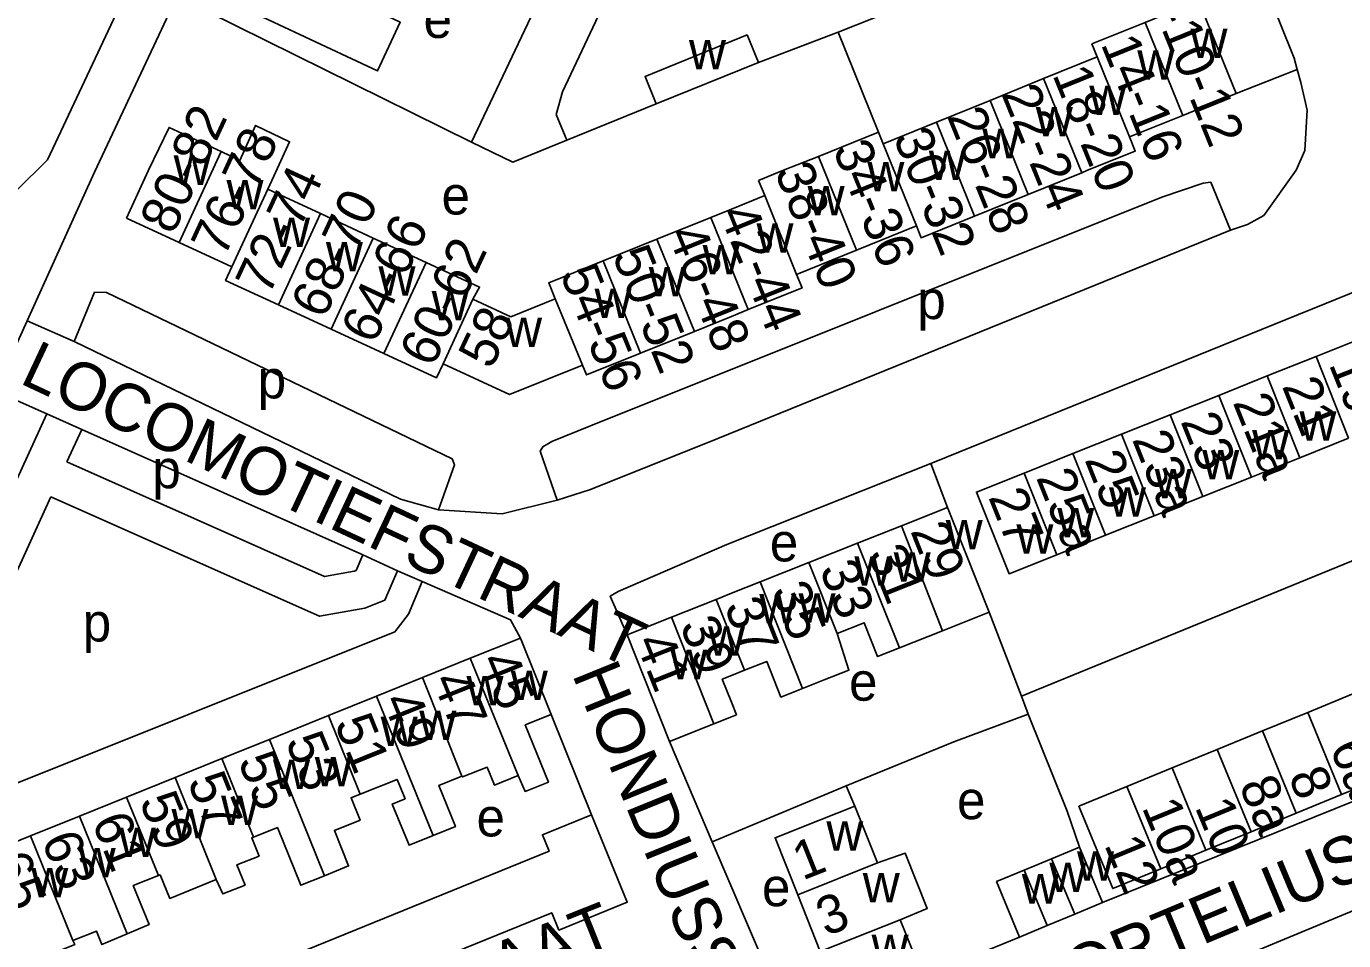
# Model space of a CAD drawing. Extents: x 163026 to 166241, y 382475 to 384501.
# Drawn here: x 163806.9 to 163944.7, y 383919.4 to 384015.1 of the extents above; entities that cross this region are included whole.
import ezdxf

# ---------------------------------------------------------------- set-up
doc = ezdxf.new("R2010")
doc.units = 0
for name, color, linetype in [('BLT_Basislijn', 7, 'Continuous'), ('BLT_Bebouwing', 7, 'Continuous'), ('BLT_Centroide', 7, 'Continuous'), ('BLT_Huisnummer', 7, 'Continuous'), ('BLT_Huisnummer_ tussenligend', 7, 'Continuous'), ('BLT_Huisnummer_reeks', 7, 'Continuous'), ('BLT_Huisnummer_zonder_bebouwing', 7, 'Continuous'), ('BLT_Onderverdeling_panden', 7, 'Continuous'), ('BLT_Plantopo', 7, 'Continuous'), ('BLT_Straatnaam', 7, 'Continuous')]:
    doc.layers.add(name, color=color, linetype=linetype)

msp = doc.modelspace()

# ---------------------------------------------------------------- linework, layer by layer
at = {"layer": 'BLT_Basislijn'}
for p, q in [((163822.68, 384018.2), (163814.06, 383999.82)), ((163853.46, 384002.93), (163822.68, 384018.2)), ((163883.46, 384011.27), (163891.79, 384014.44)), ((163891.79, 384014.44), (163896.01, 384003.99)), ((163939.8, 384010.54), (163933.41, 384008.02)), ((163863.43, 384003.15), (163872.79, 384006.94)), ((163814.06, 383999.82), (163812.81, 383997.06)), ((163812.81, 383997.06), (163807.01, 383984.26)), ((163807.01, 383984.26), (163798.24, 383964.9)), ((163807.01, 383984.26), (163811.92, 383982.1)), ((163805.38, 383976.17), (163809.07, 383974.52)), ((163809.07, 383974.52), (163812.72, 383972.89)), ((163812.72, 383972.89), (163811.17, 383969.49)), ((163812.72, 383972.89), (163842.1, 383959.76)), ((163903.22, 383964.72), (163901.49, 383969.32)), ((163910.96, 383944.99), (163964.68, 383966.99)), ((163842.1, 383959.76), (163845.75, 383958.12)), ((163845.75, 383958.12), (163848.3, 383956.98)), ((163907.58, 383953.77), (163910.96, 383944.99)), ((163910.96, 383944.99), (163911.68, 383943.1)), ((163973.09, 383945.13), (163919.45, 383923.39)), ((163861.81, 383943.08), (163866.03, 383932.58)), ((163911.68, 383943.1), (163915.75, 383932.97)), ((163878.64, 383929.76), (163874.16, 383940.26)), ((163878.64, 383929.76), (163892.65, 383935.62)), ((163893.55, 383933.49), (163892.65, 383935.62)), ((163915.75, 383932.97), (163917.04, 383929.2)), ((163887.14, 383909.88), (163878.64, 383929.76)), ((163910.78, 383919.79), (163900.66, 383915.67))]:
    msp.add_line(p, q, dxfattribs=at)
for points in [[(163849.01, 384085.89), (163834.84, 384059.46), (163835.45, 384057.42), (163823.21, 384031.1), (163809.15, 384001.11), (163805.88, 383997.85)], [(163891.79, 384014.44), (163932, 384030.42), (163939.47, 384011.72), (163939.8, 384010.54)], [(163932.83, 383993.75), (163934.6, 383994.33), (163936.29, 383995.28), (163939.69, 384000.03), (163940.6, 384002.07), (163940.83, 384006.3), (163940.18, 384009.18), (163939.8, 384010.54)], [(163932.83, 383993.75), (163930.75, 383998.76), (163929.95, 383998.65), (163925.64, 383997.2), (163865.91, 383973.26), (163861.88, 383971.64), (163860.92, 383971.09), (163860.66, 383970.61), (163862.44, 383965.48)], [(163932.83, 383993.75), (163879.24, 383971.93), (163865.91, 383966.6), (163862.44, 383965.48)], [(163901.49, 383969.32), (163901.85, 383969.47), (163945.25, 383987.07), (163951.25, 383989.73)], [(163850.03, 383964.5), (163851.68, 383969.18), (163851.45, 383969.82), (163815.33, 383987.21), (163814.07, 383987.25), (163811.92, 383982.1)], [(163850.03, 383964.5), (163846.04, 383965.59), (163811.92, 383982.1)], [(163809.07, 383974.52), (163799.29, 383953.15), (163799.06, 383947.15), (163796.84, 383942.1)], [(163811.17, 383969.49), (163838.11, 383957.51), (163841.22, 383958.06), (163841.41, 383958.14), (163842.1, 383959.76)], [(163869.73, 383951.42), (163867.98, 383955.44), (163868.8, 383955.94), (163880.15, 383960.86), (163901.49, 383969.32)], [(163809.5, 383965.86), (163803.25, 383952.2), (163803.02, 383946.24), (163798.77, 383936.55)], [(163809.5, 383965.86), (163837.6, 383953.36), (163842.32, 383954.2), (163844.43, 383955.04), (163845.75, 383958.12)], [(163850.03, 383964.5), (163856.68, 383964.07), (163862.44, 383965.48)], [(163848.3, 383956.98), (163846.88, 383953.58), (163845.46, 383951.72), (163802.6, 383934.57), (163799.82, 383935.23), (163798.77, 383936.55)], [(163858.58, 383951.07), (163857.56, 383952.97), (163848.3, 383956.98)], [(163892.65, 383935.62), (163903.91, 383940.21), (163911.68, 383943.1)], [(163922.9, 383913.1), (163924.05, 383913.58), (163964.39, 383930.36)]]:
    msp.add_lwpolyline(points, dxfattribs=at)
at = {"layer": 'BLT_Bebouwing'}
for p, q in [((163923.89, 384015.48), (163918.32, 384013.22)), ((163918.87, 384011.86), (163918.32, 384013.22)), ((163872.79, 384006.94), (163883.46, 384011.27)), ((163918.87, 384011.86), (163913.27, 384009.59)), ((163913.27, 384009.59), (163907.68, 384007.32)), ((163907.68, 384007.32), (163902.08, 384005.05)), ((163927.83, 384005.75), (163933.41, 384008.02)), ((163922.26, 384003.49), (163927.83, 384005.75)), ((163902.08, 384005.05), (163896.5, 384002.78)), ((163896.01, 384003.99), (163889.75, 384001.46)), ((163896.5, 384002.78), (163896.01, 384003.99)), ((163832.18, 383998.03), (163832.82, 383999.4)), ((163884.13, 383997.36), (163883.49, 383998.94)), ((163917.27, 383999.74), (163911.67, 383997.48)), ((163837.7, 383995.47), (163832.18, 383998.03)), ((163911.67, 383997.48), (163906.07, 383995.21)), ((163822.9, 383992.46), (163817.39, 383995.01)), ((163843.21, 383992.92), (163837.7, 383995.47)), ((163878.5, 383995.08), (163872.86, 383992.8)), ((163899.98, 383994.18), (163893.72, 383991.64)), ((163828.42, 383989.9), (163822.9, 383992.46)), ((163848.72, 383990.37), (163843.21, 383992.92)), ((163872.86, 383992.8), (163867.23, 383990.52)), ((163893.72, 383991.64), (163887.46, 383989.11)), ((163838.79, 383983.39), (163833.28, 383985.94)), ((163844.3, 383980.84), (163838.79, 383983.39)), ((163876.77, 383983.15), (163871.14, 383980.87)), ((163941.76, 383980.52), (163946.84, 383982.55)), ((163936.67, 383978.49), (163941.76, 383980.52)), ((163931.59, 383976.46), (163936.67, 383978.49)), ((163926.51, 383974.43), (163931.59, 383976.46)), ((163921.42, 383972.4), (163926.51, 383974.43)), ((163916.34, 383970.36), (163921.42, 383972.4)), ((163945.17, 383971.97), (163940.08, 383969.94)), ((163911.25, 383968.33), (163916.34, 383970.36)), ((163940.08, 383969.94), (163935, 383967.91)), ((163935, 383967.91), (163929.92, 383965.88)), ((163929.92, 383965.88), (163924.83, 383963.85)), ((163903.22, 383964.72), (163898.43, 383962.82)), ((163924.83, 383963.85), (163919.75, 383961.82)), ((163898.43, 383962.82), (163893.83, 383960.99)), ((163919.75, 383961.82), (163914.67, 383959.79)), ((163893.83, 383960.99), (163888.74, 383958.97)), ((163888.74, 383958.97), (163883.65, 383956.95)), ((163879.06, 383955.12), (163874.38, 383953.27)), ((163874.38, 383953.27), (163869.73, 383951.42)), ((163858.58, 383951.07), (163853.35, 383948.96)), ((163858.58, 383951.07), (163861.81, 383943.08)), ((163869.73, 383951.42), (163874.16, 383940.26)), ((163853.35, 383948.96), (163848.35, 383946.94)), ((163848.35, 383946.94), (163843.55, 383945)), ((163843.55, 383945), (163838.51, 383942.96)), ((163838.51, 383942.96), (163832.34, 383940.47)), ((163874.16, 383940.26), (163878.81, 383942.11)), ((163832.34, 383940.47), (163827.37, 383938.46)), ((163827.38, 383938.46), (163822.48, 383936.48)), ((163827.85, 383938.66), (163827.34, 383938.45)), ((163822.48, 383936.48), (163817.42, 383934.44)), ((163817.42, 383934.44), (163812.48, 383932.44)), ((163895.92, 383927.55), (163893.55, 383933.49)), ((163812.48, 383932.44), (163807.36, 383930.37)), ((163807.36, 383930.37), (163802.03, 383928.22)), ((163917.04, 383929.2), (163919.45, 383923.39)), ((163887.58, 383924.22), (163889.94, 383918.28)), ((163919.45, 383923.39), (163916.54, 383922.18)), ((163916.54, 383922.18), (163913.67, 383920.99)), ((163913.67, 383920.99), (163910.78, 383919.79))]:
    msp.add_line(p, q, dxfattribs=at)
for points in [[(163901.48, 384026.31), (163882.18, 384019.8), (163881.99, 384020.3), (163878.85, 384019.21), (163877.95, 384021.4), (163871.44, 384018.65), (163870.9, 384019.94), (163867.9, 384018.68), (163862.99, 384008.21), (163862.34, 384005.84), (163863.43, 384003.15)], [(163842.83, 384016.99), (163846.03, 384015.49), (163843.65, 384010.4), (163840.45, 384011.9), (163827.33, 384018.08), (163829.69, 384023.13)], [(163853.46, 384002.93), (163863.25, 384023.62)], [(163933.41, 384008.02), (163929.46, 384017.74), (163924.83, 384015.86), (163923.89, 384015.48)], [(163872.79, 384006.94), (163871.62, 384009.83), (163882.28, 384014.16), (163883.46, 384011.27)], [(163817.39, 383995.01), (163819.7, 384000), (163821.85, 384004.49), (163826.4, 384002.38), (163827.31, 384001.96)], [(163827.31, 384001.96), (163829.27, 384001.02), (163830.9, 384004.7), (163834.46, 384002.99), (163832.82, 383999.4)], [(163863.43, 384003.15), (163857.81, 384000.87), (163853.46, 384002.93)], [(163922.26, 384003.49), (163922.86, 384002.02), (163917.87, 384000), (163917.27, 383999.74)], [(163889.75, 384001.46), (163886.1, 384000), (163883.49, 383998.94)], [(163884.13, 383997.36), (163880.64, 383995.95), (163878.5, 383995.08)], [(163906.07, 383995.21), (163900.47, 383992.95), (163899.98, 383994.18)], [(163833.28, 383985.94), (163827.77, 383988.49), (163828.42, 383989.9)], [(163853.63, 383986.52), (163854.31, 383987.78), (163848.72, 383990.37)], [(163867.23, 383990.52), (163861.55, 383988.22), (163862.23, 383986.56)], [(163887.46, 383989.11), (163888.03, 383987.7), (163882.4, 383985.43)], [(163862.23, 383986.56), (163857.59, 383984.68), (163853.63, 383986.52)], [(163882.4, 383985.43), (163880.64, 383984.71), (163876.77, 383983.15)], [(163850.5, 383979.76), (163849.81, 383978.28), (163844.3, 383980.84)], [(163865.08, 383979.63), (163857.44, 383976.54), (163850.5, 383979.76)], [(163871.14, 383980.87), (163865.5, 383978.59), (163865.08, 383979.63)], [(163911.25, 383968.33), (163906.26, 383966.34), (163909.68, 383957.8), (163914.67, 383959.79)], [(163907.58, 383953.77), (163905.07, 383960.08), (163903.22, 383964.72)], [(163883.65, 383956.95), (163880.64, 383955.75), (163879.06, 383955.12)], [(163907.58, 383953.77), (163902.71, 383951.84)], [(163898.23, 383950.06), (163895.92, 383949.14), (163894.52, 383952.67), (163891.69, 383951.54)], [(163891.69, 383951.54), (163892.93, 383947.72), (163890.34, 383946.69), (163888.08, 383945.79)], [(163902.71, 383951.84), (163898.23, 383950.06)], [(163888.08, 383945.79), (163885.82, 383944.89), (163884.34, 383948.62), (163882.01, 383947.7)], [(163882.01, 383947.7), (163880.64, 383947.15), (163879.69, 383946.77), (163880.64, 383944.37), (163881.17, 383943.05), (163880.64, 383942.84), (163878.81, 383942.11)], [(163861.81, 383943.08), (163859.1, 383941.99), (163861.51, 383936.01), (163859.07, 383935.02), (163858.35, 383936.69)], [(163858.35, 383936.69), (163855.87, 383935.69), (163855.1, 383937.57), (163852.54, 383936.54), (163852.48, 383936.64)], [(163849.46, 383930.4), (163846.94, 383929.39), (163845.19, 383933.71), (163846.53, 383934.26), (163845.7, 383936.29), (163841.84, 383934.73)], [(163852.48, 383936.64), (163850.05, 383935.66), (163851.79, 383931.35), (163849.46, 383930.4)], [(163841.84, 383934.73), (163840.88, 383934.34), (163841.83, 383932.01), (163839.14, 383930.93), (163840.63, 383927.24), (163838.1, 383926.21)], [(163893.55, 383933.49), (163889.85, 383932.01), (163885.21, 383930.16), (163887.58, 383924.22)], [(163803.74, 383905.23), (163861.59, 383928.76), (163860.89, 383930.49), (163866.03, 383932.58)], [(163866.03, 383932.58), (163869.75, 383923.44), (163862.61, 383920.53), (163861.87, 383922.34), (163806.02, 383899.63)], [(163830.7, 383930.24), (163830.5, 383930.16), (163831.26, 383928.27), (163828.95, 383927.35), (163829.8, 383925.23), (163827.48, 383924.31), (163826.79, 383925.8)], [(163838.1, 383926.21), (163835.63, 383925.22), (163833.19, 383931.25), (163830.7, 383930.24)], [(163914.12, 383927.99), (163917.04, 383929.2)], [(163898.29, 383921.61), (163901.12, 383922.79), (163898.82, 383928.56), (163895.92, 383927.55)], [(163911.26, 383926.8), (163914.12, 383927.99)], [(163820.74, 383926.23), (163818.12, 383925.17), (163819.77, 383921.09), (163817.46, 383920.12)], [(163826.79, 383925.8), (163821.92, 383923.83), (163820.92, 383926.3), (163820.74, 383926.23)], [(163910.78, 383919.79), (163908.37, 383925.6), (163911.26, 383926.8)], [(163817.46, 383920.12), (163814.84, 383919.01), (163814.27, 383920.42), (163811.79, 383919.42)], [(163900.66, 383915.67), (163898.8, 383920.32), (163898.29, 383921.61)], [(163811.79, 383919.42), (163812, 383919.01), (163806.63, 383916.84), (163805.21, 383920.35)]]:
    msp.add_lwpolyline(points, dxfattribs=at)
at = {"layer": 'BLT_Onderverdeling_panden'}
for p, q in [((163927.83, 384005.75), (163923.89, 384015.48)), ((163922.26, 384003.49), (163918.87, 384011.86)), ((163917.27, 383999.74), (163913.27, 384009.59)), ((163911.67, 383997.48), (163907.68, 384007.32)), ((163906.07, 383995.21), (163902.08, 384005.05)), ((163822.9, 383992.46), (163827.31, 384001.96)), ((163899.98, 383994.18), (163896.5, 384002.78)), ((163893.72, 383991.64), (163889.75, 384001.46)), ((163828.42, 383989.9), (163832.18, 383998.03)), ((163887.46, 383989.11), (163884.13, 383997.36)), ((163833.28, 383985.94), (163837.7, 383995.47)), ((163882.4, 383985.43), (163878.5, 383995.08)), ((163838.79, 383983.39), (163843.21, 383992.92)), ((163876.77, 383983.15), (163872.86, 383992.8)), ((163844.3, 383980.84), (163848.72, 383990.37)), ((163871.14, 383980.87), (163867.23, 383990.52)), ((163853.63, 383986.52), (163850.5, 383979.76)), ((163862.23, 383986.56), (163865.08, 383979.63)), ((163941.76, 383980.52), (163945.17, 383971.97)), ((163940.08, 383969.94), (163936.67, 383978.49)), ((163931.59, 383976.46), (163935, 383967.91)), ((163929.92, 383965.88), (163926.51, 383974.43)), ((163921.42, 383972.4), (163924.83, 383963.85)), ((163919.75, 383961.82), (163916.34, 383970.36)), ((163911.25, 383968.33), (163914.67, 383959.79)), ((163902.71, 383951.84), (163898.43, 383962.82)), ((163898.23, 383950.06), (163893.83, 383960.99)), ((163891.69, 383951.54), (163888.74, 383958.97)), ((163888.08, 383945.79), (163883.65, 383956.95)), ((163882.01, 383947.7), (163879.06, 383955.12)), ((163878.81, 383942.11), (163874.38, 383953.27)), ((163858.35, 383936.69), (163853.35, 383948.96)), ((163852.48, 383936.64), (163848.35, 383946.94)), ((163849.46, 383930.4), (163843.55, 383945)), ((163841.84, 383934.73), (163838.51, 383942.96)), ((163838.1, 383926.21), (163832.34, 383940.47)), ((163830.7, 383930.24), (163827.38, 383938.46)), ((163826.79, 383925.8), (163822.48, 383936.48)), ((163820.74, 383926.23), (163817.42, 383934.44)), ((163817.46, 383920.12), (163812.48, 383932.44)), ((163811.79, 383919.42), (163807.36, 383930.37)), ((163895.92, 383927.55), (163887.58, 383924.22)), ((163916.54, 383922.18), (163914.12, 383927.99)), ((163913.67, 383920.99), (163911.26, 383926.8)), ((163898.29, 383921.61), (163889.94, 383918.28))]:
    msp.add_line(p, q, dxfattribs=at)
at = {"layer": 'BLT_Plantopo'}
for p, q in [((163940.89, 383943.3), (163945.6, 383945.24)), ((163936.17, 383941.36), (163940.89, 383943.3)), ((163940.89, 383943.3), (163944.43, 383934.69)), ((163931.44, 383939.42), (163936.17, 383941.36)), ((163939.7, 383932.75), (163936.17, 383941.36)), ((163926.72, 383937.48), (163931.44, 383939.42)), ((163931.44, 383939.42), (163934.97, 383930.81)), ((163922, 383935.55), (163926.72, 383937.48)), ((163926.72, 383937.48), (163930.25, 383928.87)), ((163925.54, 383926.93), (163922, 383935.55)), ((163944.43, 383934.69), (163949.14, 383936.63)), ((163939.7, 383932.75), (163944.43, 383934.69)), ((163934.97, 383930.81), (163939.7, 383932.75)), ((163930.25, 383928.87), (163934.97, 383930.81)), ((163930.25, 383928.87), (163925.54, 383926.93))]:
    msp.add_line(p, q, dxfattribs=at)
msp.add_lwpolyline([(163922, 383935.55), (163916.98, 383933.48), (163920.51, 383924.87), (163925.54, 383926.93)], dxfattribs=at)

# ---------------------------------------------------------------- texts
at = {"layer": 'BLT_Centroide'}
for s, p in [('e', (163848.46, 384013.85)), ('w', (163928.64, 384011.75)), ('w', (163876.21, 384010.56)), ('w', (163923.08, 384009.48)), ('w', (163918.06, 384005.8)), ('w', (163912.47, 384003.55)), ('w', (163906.88, 384001.27)), ('w', (163901.28, 383999)), ('w', (163822.34, 383998.48)), ('w', (163894.86, 383997.81)), ('w', (163827.86, 383995.92)), ('e', (163850.34, 383995.38)), ('w', (163888.61, 383995.28)), ('w', (163832.73, 383991.98)), ('w', (163883.27, 383991.39)), ('w', (163838.25, 383989.44)), ('w', (163877.64, 383989.11)), ('w', (163843.75, 383986.88)), ('w', (163872, 383986.83)), ('w', (163849.31, 383984.31)), ('w', (163866.34, 383984.55)), ('p', (163900.08, 383984.44)), ('w', (163856.99, 383981.53)), ('p', (163831.12, 383976.14)), ('w', (163940.03, 383971.72)), ('w', (163935.09, 383969.75)), ('w', (163929.87, 383967.66)), ('p', (163820.11, 383966.74)), ('w', (163924.9, 383965.67)), ('w', (163920.12, 383963.77)), ('w', (163914.71, 383961.61)), ('w', (163903.05, 383960.36)), ('e', (163884.66, 383959.09)), ('w', (163910.44, 383959.9)), ('w', (163893.5, 383956.56)), ('w', (163897.61, 383956.98)), ('w', (163883.56, 383952.61)), ('w', (163887.67, 383952.67)), ('p', (163812.83, 383950.71)), ('w', (163878.2, 383949.22)), ('w', (163874.27, 383946.77)), ('w', (163852.95, 383944.02)), ('w', (163857.58, 383944.58)), ('e', (163892.94, 383944.52)), ('w', (163843.98, 383939.77)), ('w', (163848.02, 383940.39)), ('w', (163832.73, 383935.27)), ('w', (163837.09, 383935.55)), ('w', (163827.3, 383931.5)), ('e', (163904.23, 383932.12)), ('w', (163822.11, 383930.12)), ('e', (163854, 383930.32)), ('w', (163890.57, 383928.84)), ('w', (163816.61, 383928.17)), ('w', (163812.41, 383926.05)), ('w', (163916.78, 383925.69)), ('w', (163913.89, 383924.5)), ('w', (163807.45, 383923.95)), ('e', (163883.84, 383923.02)), ('w', (163894.38, 383923.41)), ('w', (163911.02, 383923.3)), ('w', (163895.3, 383916.97))]:
    msp.add_text(s, height=4, dxfattribs=at).set_placement(p)
at = {"layer": 'BLT_Huisnummer'}
for s, rotation, p in [('58', 64.7309, (163855.55, 383979.06)), ('19a', 291.7747, (163943.07, 383979.73)), ('21', 291.7747, (163938.17, 383977.44)), ('21a', 291.7747, (163933.03, 383975.74)), ('23', 291.7747, (163927.57, 383973.75)), ('23a', 291.7747, (163922.5, 383971.87)), ('25', 291.7747, (163917.53, 383969.76)), ('25a', 291.7747, (163912.46, 383967.88)), ('27', 291.7747, (163907.47, 383965.83)), ('29', 291.6596, (163899.32, 383962.29)), ('33', 291.6577, (163889.81, 383958.29)), ('37', 291.6869, (163879.85, 383954.4)), ('41', 291.6658, (163870.56, 383950.69)), ('45', 292.0089, (163854.29, 383948.74)), ('49', 292.0089, (163844.12, 383944.52)), ('53', 292.0089, (163833.98, 383940.27)), ('57', 292.0089, (163823.74, 383936.08)), ('61', 292.0089, (163813.74, 383931.87)), ('1', 21.7339, (163888.07, 383925.68)), ('3', 21.7339, (163890.53, 383919.83))]:
    msp.add_text(s, height=4, rotation=rotation, dxfattribs=at).set_placement(p)
at = {"layer": 'BLT_Huisnummer_ tussenligend'}
for s, rotation, p in [('31', 291.6596, (163894.86, 383959.9)), ('35', 291.6577, (163884.76, 383956.04)), ('39', 291.6869, (163875.22, 383952.42)), ('47', 292.0089, (163849.33, 383946.65)), ('51', 292.0089, (163839.11, 383942.16)), ('55', 292.0089, (163829.02, 383938.22)), ('59', 292.0089, (163818.71, 383934.02)), ('63', 292.0089, (163808.47, 383929.92)), ('65', 292.0089, (163803.25, 383927.77))]:
    msp.add_text(s, height=4, rotation=rotation, dxfattribs=at).set_placement(p)
at = {"layer": 'BLT_Huisnummer_reeks'}
for s, rotation, p in [('8-10-12', 292.1015, (163923.78, 384019.25)), ('14-16', 292.0275, (163919.23, 384013.23)), ('18-20', 292.0741, (163914.17, 384010.02)), ('22-24', 292.0729, (163908.83, 384008.03)), ('80-82', 65.1484, (163822.27, 383993.15)), ('26-28', 292.0682, (163903.16, 384005.66)), ('76-78', 65.144, (163827.63, 383990.79)), ('30-32', 292.0306, (163897.52, 384003.49)), ('34-36', 292.0256, (163891.21, 384002.21)), ('72-74', 65.1498, (163832.28, 383986.78)), ('38-40', 292.0287, (163885.12, 383999.88)), ('68-70', 65.1498, (163838.07, 383984.32)), ('64-66', 65.14, (163843.31, 383981.68)), ('42-44', 292.0282, (163879.33, 383995.48)), ('46-48', 292.0261, (163873.93, 383993.34)), ('60-62', 65.14, (163849.43, 383979.26)), ('50-52', 292.0282, (163868.15, 383991.14)), ('54-56', 292.02, (163862.69, 383989.19))]:
    msp.add_text(s, height=4, rotation=rotation, dxfattribs=at).set_placement(p)
at = {"layer": 'BLT_Huisnummer_zonder_bebouwing'}
for s, p in [('6a', (163943.15, 383939.6)), ('8', (163938.83, 383936.62)), ('8a', (163933.67, 383935.68)), ('10a', (163923.52, 383933.37)), ('10', (163929.06, 383933.4)), ('12', (163919.59, 383929.46))]:
    msp.add_text(s, height=4, rotation=292.4972, dxfattribs=at).set_placement(p)
at = {"layer": 'BLT_Straatnaam'}
for s, rotation, p in [('LOCOMOTIEFSTRAAT', 334.9077, (163806.09, 383977.79)), ('HONDIUSSTRAAT', 292.1655, (163863.95, 383947.3)), ('ORTELIUSWEG', 22.64, (163916.83, 383913.49)), ('VERHEESSTRAAT', 21.7329, (163814.65, 383897.31))]:
    msp.add_text(s, height=5, rotation=rotation, dxfattribs=at).set_placement(p)

doc.saveas('drawing.dxf')
